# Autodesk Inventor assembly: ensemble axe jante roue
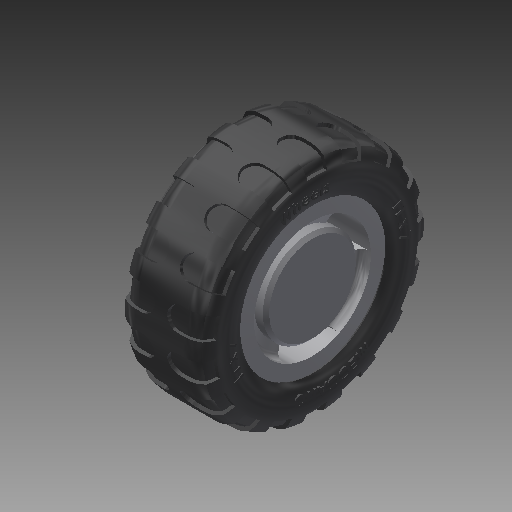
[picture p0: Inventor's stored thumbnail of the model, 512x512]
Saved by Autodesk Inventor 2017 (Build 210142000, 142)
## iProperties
Part Number: ensemble axe jante roue
Material: Générique
Document SubType Name: Assembly
Designer: ficho
Author: ficho
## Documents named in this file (7)
- G:\travail\année 2017-2018\1STI2D\challenge\ensemble axe jante roue.iam
- G:\travail\année 2017-2018\1STI2D\challenge\axe motoreducteur.ipt
- G:\travail\année 2017-2018\1STI2D\challenge\pièces meccano step\A045 - MECCANO JUNIOR.ipt
- G:\travail\année 2017-2018\1STI2D\challenge\pièces meccano step\A046 - MECCANO JUNIOR.ipt
- G:\travail\année 2017-2018\1STI2D\challenge\adaptation jante axe 2.ipt
- C:\Users\ficho\OneDrive\Documents\Inventor\Content Center Files\R2017\fr-FR\ISO 4026\ISO 4026 - M4 x 5 - ISO.ipt
- G:\travail\année 2017-2018\1STI2D\challenge\bague adaptation axe jante.ipt
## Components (6 placed, 6 different names)
1. axe motoreducteur:1 — Placage:1, Placage:2
2. A045 - MECCANO JUNIOR:1 — Logement:1
3. A046 - MECCANO JUNIOR:1 — Logement:1, Placage:1, Placage:2, Affleurement:1, Logement:2
4. adaptation jante axe 2:1 — Affleurement:1, Placage:3
5. ISO 4026 M4 x 5:1 — Placage:3
6. bague adaptation axe jante:1 — Logement:2
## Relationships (6: Mate 3, Insert 2, Flush 1)
- Logement:1 [Insert]: A045 - MECCANO JUNIOR:1 ↔ A046 - MECCANO JUNIOR:1
- Placage:1 [Mate]: axe motoreducteur:1 ↔ A046 - MECCANO JUNIOR:1
- Placage:2 [Mate]: axe motoreducteur:1 ↔ A046 - MECCANO JUNIOR:1
- Affleurement:1 [Flush]: A046 - MECCANO JUNIOR:1 ↔ adaptation jante axe 2:1
- Placage:3 [Mate]: adaptation jante axe 2:1 ↔ ISO 4026 M4 x 5:1
- Logement:2 [Insert]: A046 - MECCANO JUNIOR:1 ↔ bague adaptation axe jante:1
